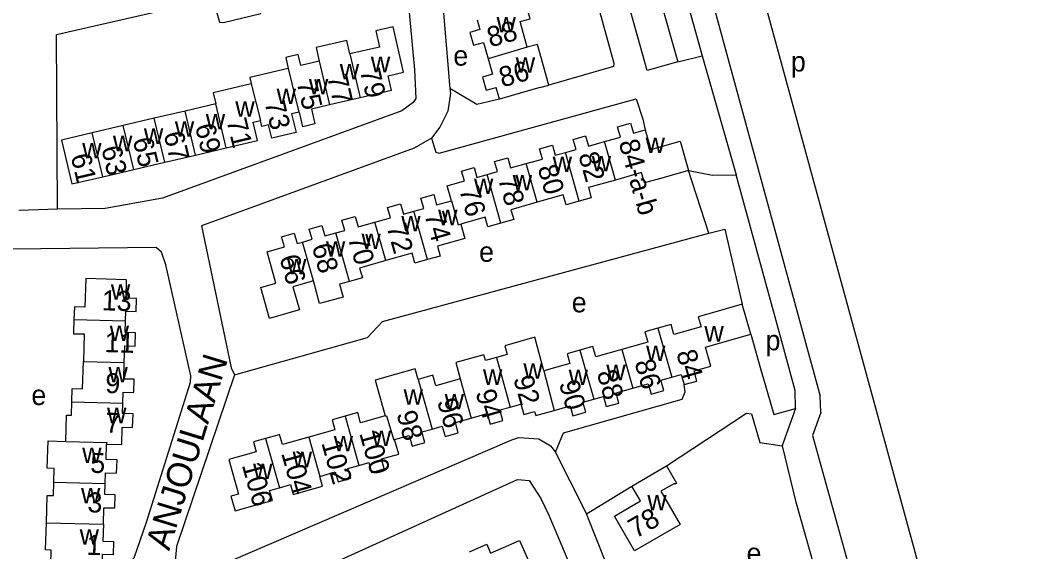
# Model space of a CAD drawing. Extents: x 157768 to 159790, y 387230 to 389604.
# Drawn here: x 159561.9 to 159765.6, y 387907.4 to 388013.4 of the extents above; entities that cross this region are included whole.
import ezdxf

# ---------------------------------------------------------------- set-up
doc = ezdxf.new("R2010")
doc.units = 0
for name, color, linetype in [('BLT_Basislijn', 7, 'Continuous'), ('BLT_Bebouwing', 7, 'Continuous'), ('BLT_Centroide', 7, 'Continuous'), ('BLT_Huisnummer', 7, 'Continuous'), ('BLT_Huisnummer_ tussenligend', 7, 'Continuous'), ('BLT_Huisnummer_reeks', 7, 'Continuous'), ('BLT_Onderverdeling_panden', 7, 'Continuous'), ('BLT_Straatnaam', 7, 'Continuous')]:
    doc.layers.add(name, color=color, linetype=linetype)

msp = doc.modelspace()

# ---------------------------------------------------------------- linework, layer by layer
at = {"layer": 'BLT_Basislijn'}
for p, q in [((159693.12, 388005.13), (159698.04, 388006.37)), ((159699.31, 387970.98), (159695.25, 387983.43)), ((159569.35, 387975.77), (159561.66, 387975.51)), ((159707.71, 387950.77), (159709.72, 387943.68)), ((159674.92, 387914.97), (159683.98, 387920.49))]:
    msp.add_line(p, q, dxfattribs=at)
for points in [[(159658.56, 388148.06), (159698.04, 388006.37)], [(159692.84, 388081.49), (159706.76, 388031.4), (159708.11, 388025.69), (159746.51, 387885.2)], [(159683.2, 388078.81), (159697.08, 388028.91), (159698.42, 388023.22), (159721.59, 387938.46)], [(159634.56, 388071.17), (159639.82, 388051.26), (159644.5, 388028.69), (159646.2, 388017.23), (159647.68, 387999.81)], [(159631.57, 388054.97), (159635.59, 388040.63), (159637.71, 388028.84), (159639.26, 388017.88), (159640.63, 388003.56), (159640.84, 387997.8), (159640.36, 387997), (159638.06, 387995.39), (159590.3, 387977.95), (159578.89, 387975.9), (159569.35, 387975.77)], [(159569.35, 387975.77), (159569.12, 388010.6), (159600.33, 388017.8), (159601.7, 388013.09), (159602.47, 388013.01), (159609.96, 388014.79), (159609.01, 388020.09), (159608.52, 388021.46), (159604.6, 388023.5), (159600.98, 388040.56), (159601, 388041.19), (159606.49, 388042.54), (159606.57, 388043.31), (159605.33, 388049.06)], [(159674.51, 388034.51), (159672.5, 388033.38), (159680.4, 388004.87), (159680.34, 388004.24), (159667.41, 388000.5)], [(159698.04, 388006.37), (159704.78, 387982.58)], [(159647.68, 387999.81), (159647.8, 387998.87), (159647.27, 387995.33), (159645.68, 387992.11), (159644.01, 387989.94)], [(159657.53, 387997.71), (159653.05, 387996.63), (159647.68, 387999.81)], [(159644.01, 387989.94), (159644.87, 387987.15), (159645.54, 387986.94), (159684.82, 387997.76), (159686.15, 387993.67), (159686.65, 387991.56)], [(159644.01, 387989.94), (159640.52, 387987.93), (159598.07, 387972.39), (159604.02, 387944.05), (159604.66, 387942.71)], [(159695.25, 387983.43), (159700.08, 387982.51), (159704.78, 387982.58)], [(159714.31, 387947.86), (159704.78, 387982.58)], [(159699.31, 387970.98), (159702.53, 387971.75), (159706.02, 387956.77)], [(159604.66, 387942.71), (159631.2, 387950.16), (159634.22, 387953.3), (159699.31, 387970.98)], [(159550.5, 387901.89), (159576.77, 387901.46), (159578.74, 387901.75), (159581.78, 387903.09), (159584.63, 387906.16), (159587.13, 387913.26), (159595.92, 387941.22), (159595.94, 387942.48), (159590.94, 387964.63), (159590.12, 387967.13), (159589.07, 387968.07), (159560.33, 387967.77)], [(159716.65, 387935.99), (159716.56, 387939.59), (159714.31, 387947.86)], [(159709.72, 387943.68), (159710.24, 387941.88), (159712.29, 387934.76), (159716.65, 387935.99)], [(159604.66, 387942.71), (159593.07, 387908.41), (159592.78, 387904.79), (159594.66, 387902.83), (159597.31, 387902.7), (159660.02, 387929.74), (159661.45, 387930.18), (159665.43, 387929.92), (159667.76, 387928.55), (159668.76, 387927.23)], [(159668.76, 387927.23), (159670.36, 387931.14), (159694.02, 387937.85), (159694.61, 387939.29), (159694.42, 387940.73)], [(159721.67, 387935.19), (159721.59, 387938.46)], [(159690.89, 387924.5), (159706.83, 387935.06), (159707.88, 387934.9), (159709.5, 387929.2), (159713.96, 387928.53)], [(159716.65, 387935.99), (159714.53, 387930.06), (159713.96, 387928.53)], [(159721.67, 387935.19), (159720.03, 387930.6)], [(159720.03, 387930.6), (159736.67, 387870.75), (159736.74, 387869.7), (159740.78, 387854.95), (159744.13, 387843.74), (159756.15, 387806.81), (159765.55, 387782.51)], [(159674.92, 387914.97), (159674.69, 387915.53), (159668.76, 387927.23)], [(159713.96, 387928.53), (159716.64, 387917.56), (159725.48, 387886.3), (159735.17, 387850.25), (159748.57, 387810.22), (159758.29, 387783.31), (159758.47, 387782.64)], [(159593.73, 387893.44), (159598.42, 387893.3), (159661.18, 387921.83), (159663.45, 387921.58), (159665.84, 387918.02), (159667.43, 387914.68), (159675.33, 387895.95), (159684.44, 387870.81), (159689.89, 387853.69)], [(159710.46, 387801.68), (159702.78, 387834.9), (159695.78, 387858.95), (159685.49, 387888.37), (159674.92, 387914.97)]]:
    msp.add_lwpolyline(points, dxfattribs=at)
at = {"layer": 'BLT_Bebouwing'}
for p, q in [((159684.13, 388037.24), (159693.12, 388005.13)), ((159665.64, 388000), (159667.41, 388000.5)), ((159635.99, 387999.43), (159629.74, 387997.97)), ((159654.9, 387999.52), (159656.88, 388000)), ((159657.53, 387997.71), (159656.88, 388000)), ((159665.64, 388000), (159657.53, 387997.71)), ((159600.94, 387996.75), (159594.81, 387995.32)), ((159629.74, 387997.97), (159623.62, 387996.53)), ((159594.81, 387995.32), (159588.63, 387993.87)), ((159582.46, 387992.42), (159576.28, 387990.98)), ((159588.63, 387993.87), (159582.46, 387992.42)), ((159590.74, 387985.11), (159596.91, 387986.55)), ((159596.91, 387986.55), (159602.98, 387987.97)), ((159584.56, 387983.66), (159590.74, 387985.11)), ((159572.22, 387980.77), (159578.39, 387982.21)), ((159578.39, 387982.21), (159584.56, 387983.66)), ((159649.86, 387972.78), (159650.67, 387969.91)), ((159707.71, 387950.77), (159706.02, 387956.77)), ((159567.47, 387929.52), (159570.99, 387929.41)), ((159683.98, 387920.49), (159690.89, 387924.5))]:
    msp.add_line(p, q, dxfattribs=at)
for points in [[(159693.12, 388005.13), (159687.03, 388003.43), (159678.05, 388035.54)], [(159663.11, 388008.05), (159661.67, 388013.16), (159663.67, 388013.72), (159662.94, 388016.32)], [(159653.11, 388013.54), (159653.66, 388011.58), (159651.61, 388011.01), (159652.34, 388008.44), (159654.39, 388009.02), (159655.32, 388005.73)], [(159635.99, 387999.43), (159635.31, 388002.33), (159638.42, 388003.06), (159636.36, 388012.13), (159632.85, 388011.3), (159633.61, 388008.09), (159627.7, 388006.71)], [(159627.7, 388006.71), (159627.06, 388009.42), (159620.94, 388007.99), (159621.58, 388005.27)], [(159667.41, 388000.5), (159665.12, 388008.61), (159663.11, 388008.05)], [(159621.58, 388005.27), (159617.92, 388004.42), (159617.4, 388006.61), (159614.95, 388006.03), (159615.4, 388003.83)], [(159655.32, 388005.73), (159656.18, 388002.66), (159654.17, 388002.09), (159654.9, 387999.52)], [(159615.4, 388003.83), (159607.71, 388002.03), (159608.02, 388000.77)], [(159608.02, 388000.77), (159600.43, 387998.98), (159600.94, 387996.75)], [(159623.62, 387996.53), (159620.05, 387995.7), (159620.73, 387992.79), (159618.33, 387992.19), (159617.64, 387995.13), (159617.5, 387995.1)], [(159617.5, 387995.1), (159616.08, 387994.77), (159616.96, 387991.02), (159612.14, 387989.89), (159611.49, 387992.55), (159610.12, 387992.22), (159609.83, 387993.43)], [(159602.98, 387987.97), (159609.25, 387989.44), (159608.4, 387993.08), (159609.83, 387993.43)], [(159678.52, 387989.24), (159681.7, 387990.14), (159681.12, 387992.19), (159683.71, 387992.91), (159684.28, 387990.9), (159686.65, 387991.56)], [(159576.28, 387990.98), (159570.16, 387989.54), (159572.22, 387980.77)], [(159670.7, 387987.06), (159672.83, 387987.65), (159672.27, 387989.65), (159674.75, 387990.35), (159675.31, 387988.34), (159678.52, 387989.24)], [(159686.65, 387991.56), (159687.75, 387987.64), (159693.6, 387989.28), (159695.25, 387983.43)], [(159662.89, 387984.83), (159666.14, 387985.75), (159665.57, 387987.78), (159668.12, 387988.5), (159668.68, 387986.49), (159670.7, 387987.06)], [(159655.09, 387982.66), (159657.13, 387983.23), (159656.56, 387985.24), (159659.21, 387985.98), (159659.78, 387983.96), (159662.89, 387984.83)], [(159647.95, 387977.43), (159647.12, 387980.41), (159650.56, 387981.37), (159650, 387983.35), (159652.48, 387984.05), (159653.03, 387982.08), (159655.09, 387982.66)], [(159695.25, 387983.43), (159690.43, 387982.08), (159686.49, 387980.97), (159685.91, 387983.03), (159680.68, 387981.56)], [(159680.68, 387981.56), (159675.31, 387980.05), (159675.88, 387978.02), (159673.44, 387977.33)], [(159640.47, 387975.35), (159642.43, 387975.9), (159641.87, 387977.91), (159644.44, 387978.64), (159645.01, 387976.61), (159647.95, 387977.43)], [(159673.44, 387977.33), (159670.85, 387976.6), (159670.3, 387978.58), (159665.07, 387977.11)], [(159632.71, 387973.16), (159635.78, 387974.03), (159635.21, 387976.05), (159637.81, 387976.79), (159638.38, 387974.76), (159640.47, 387975.35)], [(159665.07, 387977.11), (159659.83, 387975.64), (159660.39, 387973.65), (159657.82, 387972.93)], [(159624.9, 387971.01), (159626.7, 387971.51), (159626.12, 387973.56), (159628.75, 387974.3), (159629.34, 387972.22), (159632.71, 387973.16)], [(159657.82, 387972.93), (159655.26, 387972.21), (159654.71, 387974.15), (159649.86, 387972.78)], [(159618.23, 387969.19), (159620.15, 387969.73), (159619.58, 387971.76), (159622.13, 387972.47), (159622.71, 387970.39), (159624.9, 387971.01)], [(159620.42, 387961.42), (159616.34, 387960.27), (159617.64, 387955.65), (159616.44, 387955.31), (159611.63, 387953.96), (159609.9, 387960.11), (159612.95, 387960.97), (159611.19, 387967.24), (159614.62, 387968.2), (159614.04, 387970.24), (159616.6, 387970.96), (159617.18, 387968.9), (159618.23, 387969.19)], [(159650.67, 387969.91), (159645.16, 387968.36), (159645.72, 387966.38), (159643.19, 387965.67)], [(159643.19, 387965.67), (159640.66, 387964.96), (159640.11, 387966.95), (159634.87, 387965.48)], [(159634.87, 387965.48), (159629.64, 387964), (159630.19, 387962.05), (159627.62, 387961.33)], [(159582.91, 387953.45), (159582.97, 387955.41), (159585.07, 387955.35), (159585.14, 387957.92), (159583.02, 387957.99), (159583.12, 387961.66), (159574.98, 387961.89), (159574.81, 387956.19), (159572.71, 387956.25), (159572.63, 387953.75)], [(159627.62, 387961.33), (159625.62, 387960.76), (159626.34, 387958.2), (159621.67, 387956.91), (159620.42, 387961.42)], [(159706.02, 387956.77), (159701.21, 387955.41), (159697.22, 387954.29), (159697.79, 387952.26), (159692.36, 387950.73), (159691.79, 387952.74), (159689.18, 387952.01)], [(159572.63, 387953.75), (159572.56, 387951.25), (159572.55, 387950.9), (159574.68, 387950.84), (159574.52, 387945.37)], [(159582.66, 387945.14), (159582.76, 387948.48), (159584.85, 387948.42), (159584.93, 387951.1), (159582.85, 387951.16), (159582.91, 387953.45)], [(159689.18, 387952.01), (159686.57, 387951.28), (159687.15, 387949.22), (159681.95, 387947.76)], [(159666.38, 387943.5), (159664.59, 387950.17), (159658.63, 387948.5), (159659.12, 387946.77), (159656.94, 387946.16)], [(159694.42, 387940.73), (159696.96, 387941.44), (159696.39, 387943.47), (159699.76, 387944.41), (159698.68, 387948.23), (159707.71, 387950.77)], [(159673.62, 387947.6), (159671.04, 387946.87), (159671.58, 387944.96), (159666.38, 387943.5)], [(159681.95, 387947.76), (159676.76, 387946.3), (159676.19, 387948.32), (159673.62, 387947.6)], [(159572.18, 387937.29), (159572.26, 387939.97), (159574.36, 387939.91), (159574.52, 387945.37)], [(159656.94, 387946.16), (159654.74, 387945.54), (159654.41, 387946.71), (159648.82, 387945.14), (159649.74, 387941.86)], [(159582.41, 387937), (159582.48, 387939.21), (159584.56, 387939.15), (159584.64, 387941.79), (159582.57, 387941.85), (159582.66, 387945.14)], [(159641.31, 387941.78), (159640.73, 387943.86), (159632.75, 387941.61), (159634.75, 387934.51)], [(159649.74, 387941.86), (159644.88, 387940.49), (159644.28, 387942.61), (159641.31, 387941.78)], [(159684.14, 387940), (159687.25, 387940.88), (159687.82, 387938.86), (159690.35, 387939.58), (159689.78, 387941.61), (159691.94, 387942.22)], [(159691.94, 387942.22), (159693.85, 387942.76), (159694.42, 387940.73)], [(159676.36, 387937.84), (159678.29, 387938.38), (159678.86, 387936.35), (159681.38, 387937.06), (159680.82, 387939.07), (159684.14, 387940)], [(159570.99, 387929.41), (159571.14, 387934.64), (159572.11, 387934.61), (159572.18, 387937.29)], [(159668.5, 387935.59), (159671.65, 387936.48), (159672.21, 387934.51), (159674.77, 387935.24), (159674.21, 387937.23), (159676.36, 387937.84)], [(159579.16, 387928.85), (159582.17, 387928.76), (159582.27, 387932.27), (159584.34, 387932.21), (159584.42, 387934.89), (159582.35, 387934.95), (159582.41, 387937)], [(159634.75, 387934.51), (159629.84, 387933.12), (159629.27, 387935.14), (159626.73, 387934.42)], [(159651.93, 387934.07), (159655.12, 387934.96), (159655.71, 387932.86), (159658.23, 387933.58), (159657.64, 387935.67), (159659.72, 387936.26)], [(159659.72, 387936.26), (159661.81, 387936.85), (159662.39, 387934.77), (159664.54, 387935.38), (159664.78, 387934.54), (159668.5, 387935.59)], [(159626.73, 387934.42), (159624.18, 387933.7), (159624.73, 387931.73), (159619.49, 387930.25)], [(159644.11, 387931.85), (159646.13, 387932.42), (159646.71, 387930.36), (159649.33, 387931.1), (159648.75, 387933.17), (159651.93, 387934.07)], [(159636.63, 387929.75), (159639.52, 387930.56), (159640.12, 387928.43), (159642.69, 387929.16), (159642.09, 387931.29), (159644.11, 387931.85)], [(159568.62, 387921.29), (159568.7, 387923.99), (159567.31, 387924.03), (159567.47, 387929.52)], [(159610.89, 387929.97), (159608.48, 387929.3), (159609.03, 387927.35), (159603.54, 387925.81), (159605.48, 387918.9)], [(159619.49, 387930.25), (159614.24, 387928.78), (159613.68, 387930.76), (159613.29, 387930.65), (159610.89, 387929.97)], [(159629.48, 387924.62), (159631.45, 387925.18), (159632, 387923.23), (159634.56, 387923.95), (159634.01, 387925.9), (159637.44, 387926.87), (159636.63, 387929.75)], [(159578.84, 387921), (159578.9, 387923.1), (159581.15, 387923.04), (159581.23, 387925.72), (159579.07, 387925.78), (159579.16, 387928.85)], [(159621.69, 387922.43), (159624.79, 387923.3), (159625.35, 387921.33), (159627.87, 387922.04), (159627.32, 387924.01), (159629.48, 387924.62)], [(159690.89, 387924.5), (159692.88, 387921.06), (159692.59, 387920.9), (159692.51, 387921.03), (159689.78, 387919.45), (159693.62, 387912.83), (159684.52, 387907.55), (159680.49, 387914.5), (159685.7, 387917.52), (159683.98, 387920.49)], [(159567.12, 387913.16), (159567.28, 387918.63), (159568.55, 387918.6), (159568.62, 387921.29)], [(159578.52, 387912.86), (159578.62, 387916.18), (159580.82, 387916.12), (159580.89, 387918.75), (159578.78, 387918.81), (159578.84, 387921)], [(159613.65, 387920.17), (159615.83, 387920.78), (159616.38, 387918.83), (159618.93, 387919.55), (159622.23, 387920.47), (159621.69, 387922.43)], [(159605.48, 387918.9), (159603.97, 387918.47), (159604.79, 387915.55), (159609.74, 387916.94)], [(159609.74, 387916.94), (159612.23, 387917.64), (159611.68, 387919.61), (159613.65, 387920.17)], [(159578.52, 387912.86), (159578.42, 387909.47), (159580.55, 387909.41), (159580.48, 387906.8), (159578.29, 387906.86), (159578.22, 387904.48), (159568.02, 387904.78), (159568.1, 387907.71), (159566.96, 387907.74), (159567.12, 387913.16)], [(159651.57, 387907.36), (159655.01, 387908.88), (159655.78, 387907.12), (159661.56, 387909.66), (159664.8, 387902.29), (159660.22, 387900.27), (159658.83, 387899.66), (159659.41, 387898.35), (159656.27, 387896.97)]]:
    msp.add_lwpolyline(points, dxfattribs=at)
at = {"layer": 'BLT_Onderverdeling_panden'}
for p, q in [((159627.7, 388006.71), (159629.74, 387997.97)), ((159663.11, 388008.05), (159655.32, 388005.73)), ((159621.58, 388005.27), (159623.62, 387996.53)), ((159615.4, 388003.83), (159617.5, 387995.1)), ((159608.02, 388000.77), (159609.83, 387993.43)), ((159602.98, 387987.97), (159600.94, 387996.75)), ((159596.91, 387986.55), (159594.81, 387995.32)), ((159584.56, 387983.66), (159582.46, 387992.42)), ((159590.74, 387985.11), (159588.63, 387993.87)), ((159578.39, 387982.21), (159576.28, 387990.98)), ((159680.68, 387981.56), (159678.52, 387989.24)), ((159673.44, 387977.33), (159670.7, 387987.06)), ((159665.07, 387977.11), (159662.89, 387984.83)), ((159657.82, 387972.93), (159655.09, 387982.66)), ((159643.19, 387965.67), (159640.47, 387975.35)), ((159634.87, 387965.48), (159632.71, 387973.16)), ((159627.62, 387961.33), (159624.9, 387971.01)), ((159620.42, 387961.42), (159618.23, 387969.19)), ((159572.63, 387953.75), (159582.91, 387953.45)), ((159689.18, 387952.01), (159691.94, 387942.22)), ((159673.62, 387947.6), (159676.36, 387937.84)), ((159681.95, 387947.76), (159684.14, 387940)), ((159574.52, 387945.37), (159582.66, 387945.14)), ((159656.94, 387946.16), (159659.72, 387936.26)), ((159666.38, 387943.5), (159668.5, 387935.59)), ((159641.31, 387941.78), (159644.11, 387931.85)), ((159649.74, 387941.86), (159651.93, 387934.07)), ((159572.18, 387937.29), (159582.41, 387937)), ((159626.73, 387934.42), (159629.48, 387924.62)), ((159610.89, 387929.97), (159613.65, 387920.17)), ((159619.49, 387930.25), (159621.69, 387922.43)), ((159568.62, 387921.29), (159578.84, 387921)), ((159567.12, 387913.16), (159578.52, 387912.86))]:
    msp.add_line(p, q, dxfattribs=at)
for points in [[(159647.95, 387977.43), (159649.33, 387972.63), (159649.86, 387972.78)], [(159634.75, 387934.51), (159635.04, 387934.52), (159636.46, 387929.67), (159636.63, 387929.75)], [(159570.99, 387929.41), (159579.17, 387929.18), (159579.16, 387928.85)]]:
    msp.add_lwpolyline(points, dxfattribs=at)

# ---------------------------------------------------------------- texts
at = {"layer": 'BLT_Centroide'}
for s, p in [('w', (159656.97, 388011.03)), ('e', (159648.35, 388004.38)), ('p', (159715.72, 388003.21)), ('w', (159625.69, 388001.64)), ('w', (159631.88, 388003.08)), ('w', (159660.8, 388002.95)), ('w', (159619.52, 387998.64)), ('w', (159613.08, 387996.7)), ('w', (159604.84, 387994.17)), ('w', (159598.94, 387991.66)), ('w', (159592.77, 387990.22)), ('w', (159580.42, 387987.31)), ('w', (159586.59, 387988.77)), ('w', (159574.28, 387985.88)), ('w', (159686.72, 387986.94)), ('w', (159668.17, 387983.14)), ('w', (159675.97, 387983.28)), ('w', (159660.2, 387979.47)), ('w', (159652.47, 387978.78)), ('w', (159637.95, 387971.33)), ('w', (159645.31, 387972.55)), ('w', (159630.01, 387967.81)), ('w', (159622.92, 387966.28)), ('e', (159653.49, 387965.24)), ('w', (159615.16, 387962.75)), ('w', (159580, 387957.66)), ('e', (159671.98, 387955.15)), ('w', (159579.76, 387949.44)), ('w', (159698.45, 387949.33)), ('p', (159710.66, 387947.58)), ('w', (159686.82, 387945.44)), ('w', (159579.52, 387941.19)), ('w', (159654.27, 387940.69)), ('w', (159662.33, 387941.91)), ('w', (159671.36, 387940.66)), ('w', (159678.88, 387941.62)), ('e', (159564.14, 387936.66)), ('w', (159638.42, 387936.72)), ('w', (159646.62, 387935.81)), ('w', (159579.24, 387933.03)), ('w', (159632.08, 387928.5)), ('w', (159624.48, 387927.44)), ('w', (159574.27, 387925.09)), ('w', (159616.28, 387924.25)), ('w', (159608.39, 387921.88)), ('w', (159574.04, 387917.06)), ('w', (159687.06, 387915.66)), ('w', (159573.77, 387908.81)), ('e', (159706.87, 387905.13))]:
    msp.add_text(s, height=4, dxfattribs=at).set_placement(p)
at = {"layer": 'BLT_Huisnummer'}
for s, rotation, p in [('86', 15.7681, (159658.12, 388000.02)), ('79', 283.1802, (159629.69, 388003.4)), ('73', 283.1817, (159610.65, 387997.06)), ('71', 283.5117, (159603.04, 387993.44)), ('69', 283.5138, (159596.77, 387992.35)), ('65', 283.5138, (159584.33, 387989.61)), ('61', 283.183, (159571.96, 387986.39)), ('78', 285.6999, (159657.22, 387981.82)), ('74', 285.6999, (159642.54, 387974.66)), ('70', 285.6999, (159627.26, 387970.01)), ('66', 285.6999, (159613.59, 387966.1)), ('13', 358.3379, (159578.13, 387955.57)), ('84', 285.7186, (159692.8, 387947.12)), ('88', 285.7186, (159676.95, 387943.11)), ('9', 358.3379, (159578.85, 387939.06)), ('92', 285.7178, (159660.28, 387941.99)), ('96', 285.7252, (159645.07, 387937.45)), ('100', 285.7323, (159629.55, 387931.04)), ('5', 358.3379, (159575.85, 387923.15)), ('106', 285.7152, (159606.11, 387924.69)), ('78', 30.0317, (159684.74, 387909.94)), ('1', 358.3379, (159575.09, 387906.78))]:
    msp.add_text(s, height=4, rotation=rotation, dxfattribs=at).set_placement(p)
at = {"layer": 'BLT_Huisnummer_ tussenligend'}
for s, rotation, p in [('88', 15.7681, (159655.73, 388008.01)), ('77', 283.1817, (159623.13, 388002.18)), ('75', 283.1817, (159617.05, 388001.07)), ('67', 283.5138, (159590.49, 387990.79)), ('63', 283.183, (159578.06, 387987.94)), ('82', 285.6999, (159673.26, 387986.58)), ('80', 285.6999, (159665.14, 387984.04)), ('76', 285.6999, (159649.49, 387979.65)), ('72', 285.6999, (159634.98, 387972.27)), ('68', 285.6999, (159620.06, 387968.35)), ('11', 358.3379, (159578.71, 387947.23)), ('86', 285.7186, (159684.47, 387945.2)), ('90', 285.7178, (159669.4, 387941.04)), ('94', 285.7252, (159652.75, 387939.21)), ('7', 358.3379, (159578.87, 387931.15)), ('98', 285.7323, (159636.96, 387934.95)), ('102', 285.715, (159621.98, 387929.11)), ('104', 285.715, (159613.97, 387927.05)), ('3', 358.3379, (159575.28, 387915.27))]:
    msp.add_text(s, height=4, rotation=rotation, dxfattribs=at).set_placement(p)
at = {"layer": 'BLT_Huisnummer_reeks'}
msp.add_text('84-a-b', height=4, rotation=285.6999, dxfattribs=at).set_placement((159681.32, 387989.09))
at = {"layer": 'BLT_Straatnaam'}
msp.add_text('ANJOULAAN', height=5, rotation=72.9373, dxfattribs=at).set_placement((159591.64, 387907.45))

doc.saveas('drawing.dxf')
